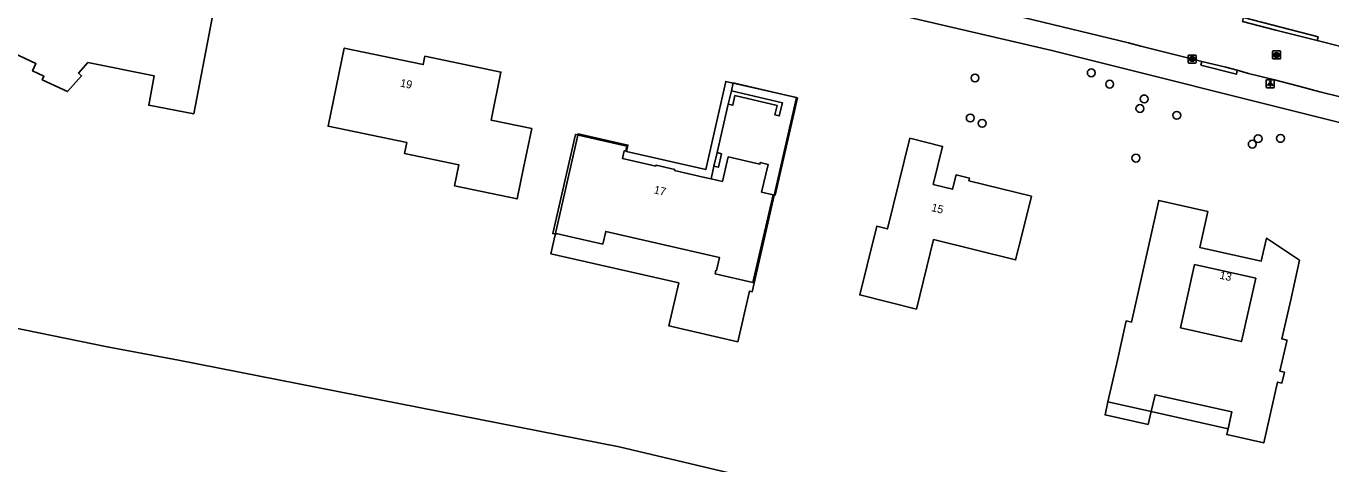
# Model space of a CAD drawing. Extents: x 161486 to 162249, y 379484 to 380829.
# Drawn here: x 161831.1 to 161994.2, y 380340.6 to 380395.2 of the extents above; entities that cross this region are included whole.
import ezdxf

# ---------------------------------------------------------------- set-up
doc = ezdxf.new("R2010")
doc.units = 0
for name, color, linetype in [('IMGEO_Boom', 7, 'Continuous'), ('IMGEO_Gemengd_bos', 7, 'Continuous'), ('IMGEO_Hek', 7, 'Continuous'), ('IMGEO_Kolk', 7, 'Continuous'), ('IMGEO_Lichtpunt', 7, 'Continuous'), ('IMGEO_Pand', 7, 'Continuous'), ('IMGEO_Pand_nummerreeks', 7, 'Continuous'), ('IMGEO_Pand_overbouw', 7, 'Continuous'), ('IMGEO_Pand_vergunning_verleend', 7, 'Continuous'), ('IMGEO_Rijbaan_lokaal_open', 7, 'Continuous'), ('IMGEO_Rioolput', 7, 'Continuous'), ('IMGEO_Voetpad_open', 7, 'Continuous')]:
    doc.layers.add(name, color=color, linetype=linetype)

msp = doc.modelspace()

# ---------------------------------------------------------------- linework, layer by layer
at = {"layer": 'IMGEO_Boom'}
for centre in [(161949.71, 380388.77), (161964.24, 380389.41), (161966.54, 380387.99), (161970.32, 380384.95), (161970.86, 380386.15), (161949.12, 380383.77), (161950.61, 380383.1), (161974.93, 380384.1), (161984.36, 380380.5), (161985.09, 380381.19), (161987.89, 380381.22), (161969.82, 380378.76)]:
    msp.add_circle(centre, 0.489, dxfattribs=at)
at = {"layer": 'IMGEO_Gemengd_bos'}
msp.add_lwpolyline([(161650, 380406.68), (161673.2, 380388.4), (161682.46, 380380.89), (161735.15, 380373.87), (161748.24, 380371.95), (161806.45, 380361.94), (161823.96, 380358.71), (161841.26, 380355.19), (161850.18, 380353.54), (161905.25, 380342.68), (161988.72, 380322.9), (161980.66, 380286.4)], dxfattribs=at)
at = {"layer": 'IMGEO_Hek'}
msp.add_lwpolyline([(161980.66, 380286.4), (161988.72, 380322.9), (161905.25, 380342.68), (161850.18, 380353.54), (161841.26, 380355.19), (161823.96, 380358.71), (161806.45, 380361.94), (161748.24, 380371.95), (161735.15, 380373.87), (161682.46, 380380.89), (161673.2, 380388.4), (161650, 380406.63), (161649.61, 380406.73)], dxfattribs=at)
at = {"layer": 'IMGEO_Kolk'}
for p, q in [((161976.42, 380391.63), (161977.28, 380391.63)), ((161976.35, 380390.71), (161976.35, 380391.56)), ((161977.28, 380390.63), (161976.42, 380390.63)), ((161976.86, 380390.85), (161976.83, 380390.85)), ((161976.84, 380391.41), (161976.86, 380391.41)), ((161977.35, 380391.56), (161977.35, 380390.71))]:
    msp.add_line(p, q, dxfattribs=at)
for points in [[(161976.42, 380391.63), (161977.28, 380391.63)], [(161976.35, 380390.71), (161976.35, 380391.56)], [(161977.28, 380390.63), (161976.42, 380390.63)], [(161976.67, 380391.33), (161976.79, 380391.33), (161976.79, 380391.18), (161976.92, 380391.33), (161977.09, 380391.33), (161976.94, 380391.18), (161977.09, 380390.93), (161976.94, 380390.93), (161976.86, 380391.1), (161976.79, 380391.03), (161976.79, 380390.93), (161976.67, 380390.93), (161976.67, 380391.33)], [(161977.35, 380391.56), (161977.35, 380390.71)]]:
    msp.add_lwpolyline(points, dxfattribs=at)
for centre, start, end in [((161976.43, 380391.56), 91.552, 178.448), ((161976.43, 380391.56), 91.552, 178.448), ((161977.27, 380391.56), 1.552, 88.448), ((161977.27, 380391.56), 1.552, 88.448), ((161976.43, 380390.71), 181.552, 268.448), ((161976.43, 380390.71), 181.552, 268.448), ((161977.27, 380390.71), 271.552, 358.448), ((161977.27, 380390.71), 271.552, 358.448)]:
    msp.add_arc(centre, 0.0765, start, end, dxfattribs=at)
for centre, major_axis, ratio, start_param, end_param in [((161976.84, 380391.13), (-0.387, 0.002), 0.722429, 4.712389, 7.853982), ((161976.86, 380391.13), (-0.39, 0.002), 0.717154, 1.570796, 4.712389)]:
    msp.add_ellipse(centre, major_axis=major_axis, ratio=ratio, start_param=start_param, end_param=end_param, dxfattribs=at)
at = {"layer": 'IMGEO_Lichtpunt'}
for p, q in [((161986.11, 380388.45), (161986.11, 380387.64)), ((161986.11, 380388.45), (161986.11, 380387.64)), ((161987.01, 380388.55), (161986.2, 380388.55)), ((161987.01, 380388.55), (161986.2, 380388.55)), ((161987.1, 380387.64), (161987.1, 380388.45)), ((161987.1, 380387.64), (161987.1, 380388.45)), ((161986.2, 380387.55), (161987.01, 380387.55)), ((161986.2, 380387.55), (161987.01, 380387.55))]:
    msp.add_line(p, q, dxfattribs=at)
for points in [[(161986.48, 380388.11), (161986.52, 380388.09), (161986.33, 380387.82), (161986.29, 380387.85), (161986.48, 380388.11)], [(161986.58, 380388.07), (161986.63, 380388.07), (161986.63, 380387.74), (161986.58, 380387.74), (161986.58, 380388.07)], [(161986.69, 380388.09), (161986.73, 380388.11), (161986.92, 380387.85), (161986.88, 380387.82), (161986.69, 380388.09)]]:
    msp.add_lwpolyline(points, dxfattribs=at)
msp.add_circle((161986.61, 380388.25), 0.0994, dxfattribs=at)
for centre, start, end in [((161986.2, 380388.45), 90, 180), ((161986.2, 380388.45), 90, 180), ((161987.01, 380388.45), 0, 90), ((161987.01, 380388.45), 0, 90), ((161986.2, 380387.64), 180, 270), ((161986.2, 380387.64), 180, 270), ((161987.01, 380387.64), 270, 0), ((161987.01, 380387.64), 270, 360)]:
    msp.add_arc(centre, 0.0946, start, end, dxfattribs=at)
at = {"layer": 'IMGEO_Pand'}
for points in [[(161852.11, 380384.29), (161846.46, 380385.36), (161847.16, 380389.03), (161838.86, 380390.68), (161837.7, 380389.37), (161838.08, 380389.04), (161836.32, 380387.06), (161833.16, 380388.54), (161833.37, 380388.99), (161831.95, 380389.65), (161832.38, 380390.56), (161826.21, 380393.44), (161828.21, 380397.72), (161830.44, 380409.21), (161837.61, 380407.82), (161836.09, 380399.83), (161847.35, 380397.66), (161849.01, 380406.11), (161856.01, 380404.78), (161852.11, 380384.29)], [(161893.3, 380377.56), (161892.49, 380373.67), (161884.66, 380375.3), (161885.21, 380377.92), (161878.44, 380379.33), (161878.73, 380380.69), (161868.87, 380382.74), (161869.88, 380387.6), (161870.9, 380392.5), (161880.76, 380390.45), (161880.97, 380391.48), (161887.73, 380390.07), (161890.48, 380389.5), (161889.24, 380383.51), (161894.32, 380382.45), (161893.3, 380377.56)], [(161919.27, 380387.15), (161918.89, 380385.5), (161919.44, 380385.37), (161919.72, 380386.57), (161924.99, 380385.34), (161924.71, 380384.15), (161925.26, 380384.02), (161925.64, 380385.67), (161919.27, 380387.15)], [(161924.5, 380374.16), (161923.05, 380374.5), (161923.86, 380377.98), (161922.89, 380378.21), (161922.84, 380377.99), (161918.88, 380378.91), (161918.16, 380375.84), (161916.74, 380376.16), (161915.74, 380376.39), (161912.17, 380377.22), (161912.2, 380377.35), (161909.86, 380377.89), (161909.83, 380377.76), (161905.66, 380378.72), (161905.88, 380379.68), (161906.08, 380379.63), (161906.22, 380380.23), (161899.8, 380381.72), (161896.95, 380369.34), (161897.36, 380369.24), (161897.39, 380369.34), (161903.2, 380368.01), (161903.57, 380369.61), (161917.43, 380366.42), (161917.8, 380366.33), (161917.43, 380364.73), (161917.33, 380364.75), (161917.23, 380364.31), (161921.97, 380363.22), (161924.5, 380374.16)], [(161936.23, 380365.4), (161937.44, 380370.25), (161938.76, 380369.92), (161941.58, 380381.24), (161945.67, 380380.22), (161944.49, 380375.47), (161946.9, 380374.87), (161947.35, 380376.66), (161949.04, 380376.24), (161948.96, 380375.94), (161956.76, 380374), (161955.55, 380369.15), (161954.78, 380366.05), (161944.54, 380368.59), (161942.39, 380359.91), (161935.31, 380361.67), (161936.23, 380365.4)], [(161918.04, 380379.31), (161917.49, 380379.44), (161917.1, 380377.75), (161917.65, 380377.62), (161918.04, 380379.31)], [(161968.59, 380358.42), (161969.26, 380358.27), (161972.68, 380373.48), (161978.8, 380372.1), (161977.79, 380367.61), (161985.49, 380365.89), (161986.14, 380368.76), (161990.27, 380366), (161989.16, 380361.07), (161988.06, 380356.17), (161988.69, 380356.03), (161988.66, 380355.91), (161987.82, 380352.16), (161988.37, 380352.04), (161988.06, 380350.66), (161987.51, 380350.79), (161985.8, 380343.18), (161981.18, 380344.22), (161981.81, 380347.05), (161972.21, 380349.21), (161971.74, 380347.1), (161966.32, 380348.32), (161967.5, 380353.54), (161968.59, 380358.42)], [(161977.15, 380365.46), (161975.38, 380357.56), (161983.01, 380355.85), (161984.79, 380363.75), (161977.15, 380365.46)]]:
    msp.add_lwpolyline(points, dxfattribs=at)
at = {"layer": 'IMGEO_Pand_overbouw'}
for points in [[(161927.55, 380386.27), (161919.51, 380388.14), (161919.27, 380387.15), (161918.89, 380385.5), (161917.49, 380379.44), (161917.1, 380377.75), (161916.74, 380376.16), (161918.16, 380375.84), (161918.88, 380378.91), (161922.84, 380377.99), (161922.89, 380378.21), (161923.86, 380377.98), (161923.05, 380374.5), (161924.5, 380374.16), (161924.73, 380374.11)], [(161971.74, 380347.1), (161981.34, 380344.95), (161981.81, 380347.05), (161972.21, 380349.21)], [(161971.37, 380345.47), (161971.74, 380347.1), (161966.32, 380348.32), (161965.96, 380346.69)]]:
    msp.add_lwpolyline(points, close=True, dxfattribs=at)
at = {"layer": 'IMGEO_Pand_vergunning_verleend'}
msp.add_lwpolyline([(161896.7, 380366.8), (161900.12, 380381.81), (161906.35, 380380.39), (161906.16, 380379.59), (161916.06, 380377.33), (161918.57, 380388.34), (161927.41, 380386.32), (161921.88, 380362.06), (161921.52, 380362.14), (161920.08, 380355.83), (161911.47, 380357.79), (161912.7, 380363.16), (161896.7, 380366.8)], dxfattribs=at)
at = {"layer": 'IMGEO_Rijbaan_lokaal_open'}
for points in [[(161978.07, 380390.83), (161975.11, 380391.57), (161970.42, 380392.72), (161968.88, 380393.15), (161955.77, 380396.34), (161948.89, 380397.98)], [(161992.46, 380393.44), (161987.29, 380394.73), (161983.13, 380395.82)], [(161992.46, 380393.44), (161995.41, 380392.71), (161996.83, 380392.35), (162000, 380391.57), (162004.96, 380390.35), (162009.39, 380389.29)], [(161978.07, 380390.83), (161981.04, 380390.13), (161982.49, 380389.73)], [(161997.05, 380386.02), (161995.69, 380386.34), (161995.49, 380386.39), (161992.81, 380387.05), (161990.18, 380387.73), (161986.97, 380388.57), (161983.88, 380389.34), (161982.49, 380389.73)]]:
    msp.add_lwpolyline(points, dxfattribs=at)
at = {"layer": 'IMGEO_Rioolput'}
for p, q in [((161986.89, 380391.22), (161986.89, 380392.07)), ((161986.97, 380392.15), (161987.82, 380392.15)), ((161987.38, 380391.92), (161987.41, 380391.92)), ((161987.89, 380392.07), (161987.89, 380391.22)), ((161987.82, 380391.14), (161986.97, 380391.14)), ((161987.4, 380391.37), (161987.38, 380391.37))]:
    msp.add_line(p, q, dxfattribs=at)
for points in [[(161986.89, 380391.22), (161986.89, 380392.07)], [(161986.97, 380392.15), (161987.82, 380392.15)], [(161987.48, 380391.84), (161987.23, 380391.84), (161987.23, 380391.44)], [(161987.23, 380391.44), (161987.35, 380391.44), (161987.35, 380391.61), (161987.37, 380391.61)], [(161987.41, 380391.76), (161987.35, 380391.76), (161987.35, 380391.68)], [(161987.35, 380391.68), (161987.41, 380391.68)], [(161987.41, 380391.58), (161987.48, 380391.44), (161987.62, 380391.44), (161987.56, 380391.57)], [(161987.89, 380392.07), (161987.89, 380391.22)], [(161987.82, 380391.14), (161986.97, 380391.14)]]:
    msp.add_lwpolyline(points, dxfattribs=at)
for centre, radius, start, end in [((161986.97, 380392.07), 0.0765, 91.552, 178.448), ((161986.97, 380392.07), 0.0765, 91.552, 178.448), ((161987.36, 380391.55), 0.0533, 26.0293, 88.6989), ((161987.41, 380391.67), 0.0964, 77.0061, 93.1865), ((161987.39, 380391.87), 0.19, 274.7715, 282.9687), ((161987.43, 380391.72), 0.0378, 276.6634, 79.6772), ((161987.48, 380391.73), 0.109, 350.3612, 89.416), ((161987.48, 380391.73), 0.112, 277.5842, 350.9817), ((161987.46, 380391.52), 0.108, 29.5134, 73.7905), ((161987.82, 380392.07), 0.0765, 1.552, 88.448), ((161987.82, 380392.07), 0.0765, 1.552, 88.448), ((161986.97, 380391.22), 0.0765, 181.552, 268.448), ((161986.97, 380391.22), 0.0765, 181.552, 268.448), ((161987.82, 380391.22), 0.0765, 271.552, 358.448), ((161987.82, 380391.22), 0.0765, 271.552, 358.448)]:
    msp.add_arc(centre, radius, start, end, dxfattribs=at)
for centre, major_axis, ratio, start_param, end_param in [((161987.38, 380391.64), (-0.387, 0.002), 0.722429, 4.712389, 7.853982), ((161987.4, 380391.64), (-0.39, 0.002), 0.717154, 1.570796, 4.712389)]:
    msp.add_ellipse(centre, major_axis=major_axis, ratio=ratio, start_param=start_param, end_param=end_param, dxfattribs=at)
at = {"layer": 'IMGEO_Voetpad_open'}
for points in [[(162198.7, 380353.09), (162194.98, 380353.34), (162177.85, 380354.25), (162167.43, 380355.08), (162143.23, 380356.61), (162124.75, 380358.41), (162101.44, 380361.32), (162078.96, 380365.04), (162051.57, 380370.41), (162025.01, 380376.15), (162000, 380382.03), (161995.1, 380383.25), (161959.32, 380392.21), (161910.21, 380403.65), (161910.18, 380403.66)], [(161983.13, 380395.82), (161983.25, 380396.3), (161992.58, 380393.92), (161992.46, 380393.44)], [(161982.49, 380389.73), (161982.37, 380389.24), (161977.95, 380390.35), (161978.07, 380390.83)]]:
    msp.add_lwpolyline(points, dxfattribs=at)

# ---------------------------------------------------------------- texts
at = {"layer": 'IMGEO_Pand_nummerreeks'}
for s, rotation, p in [('19', 348.2486, (161877.82, 380387.71)), ('17', 346.9709, (161909.52, 380374.37)), ('15', 346.0364, (161944.19, 380372.16)), ('13', 347.3376, (161980.21, 380363.71))]:
    msp.add_text(s, height=1, rotation=rotation, dxfattribs=at).set_placement(p)

doc.saveas('drawing.dxf')
